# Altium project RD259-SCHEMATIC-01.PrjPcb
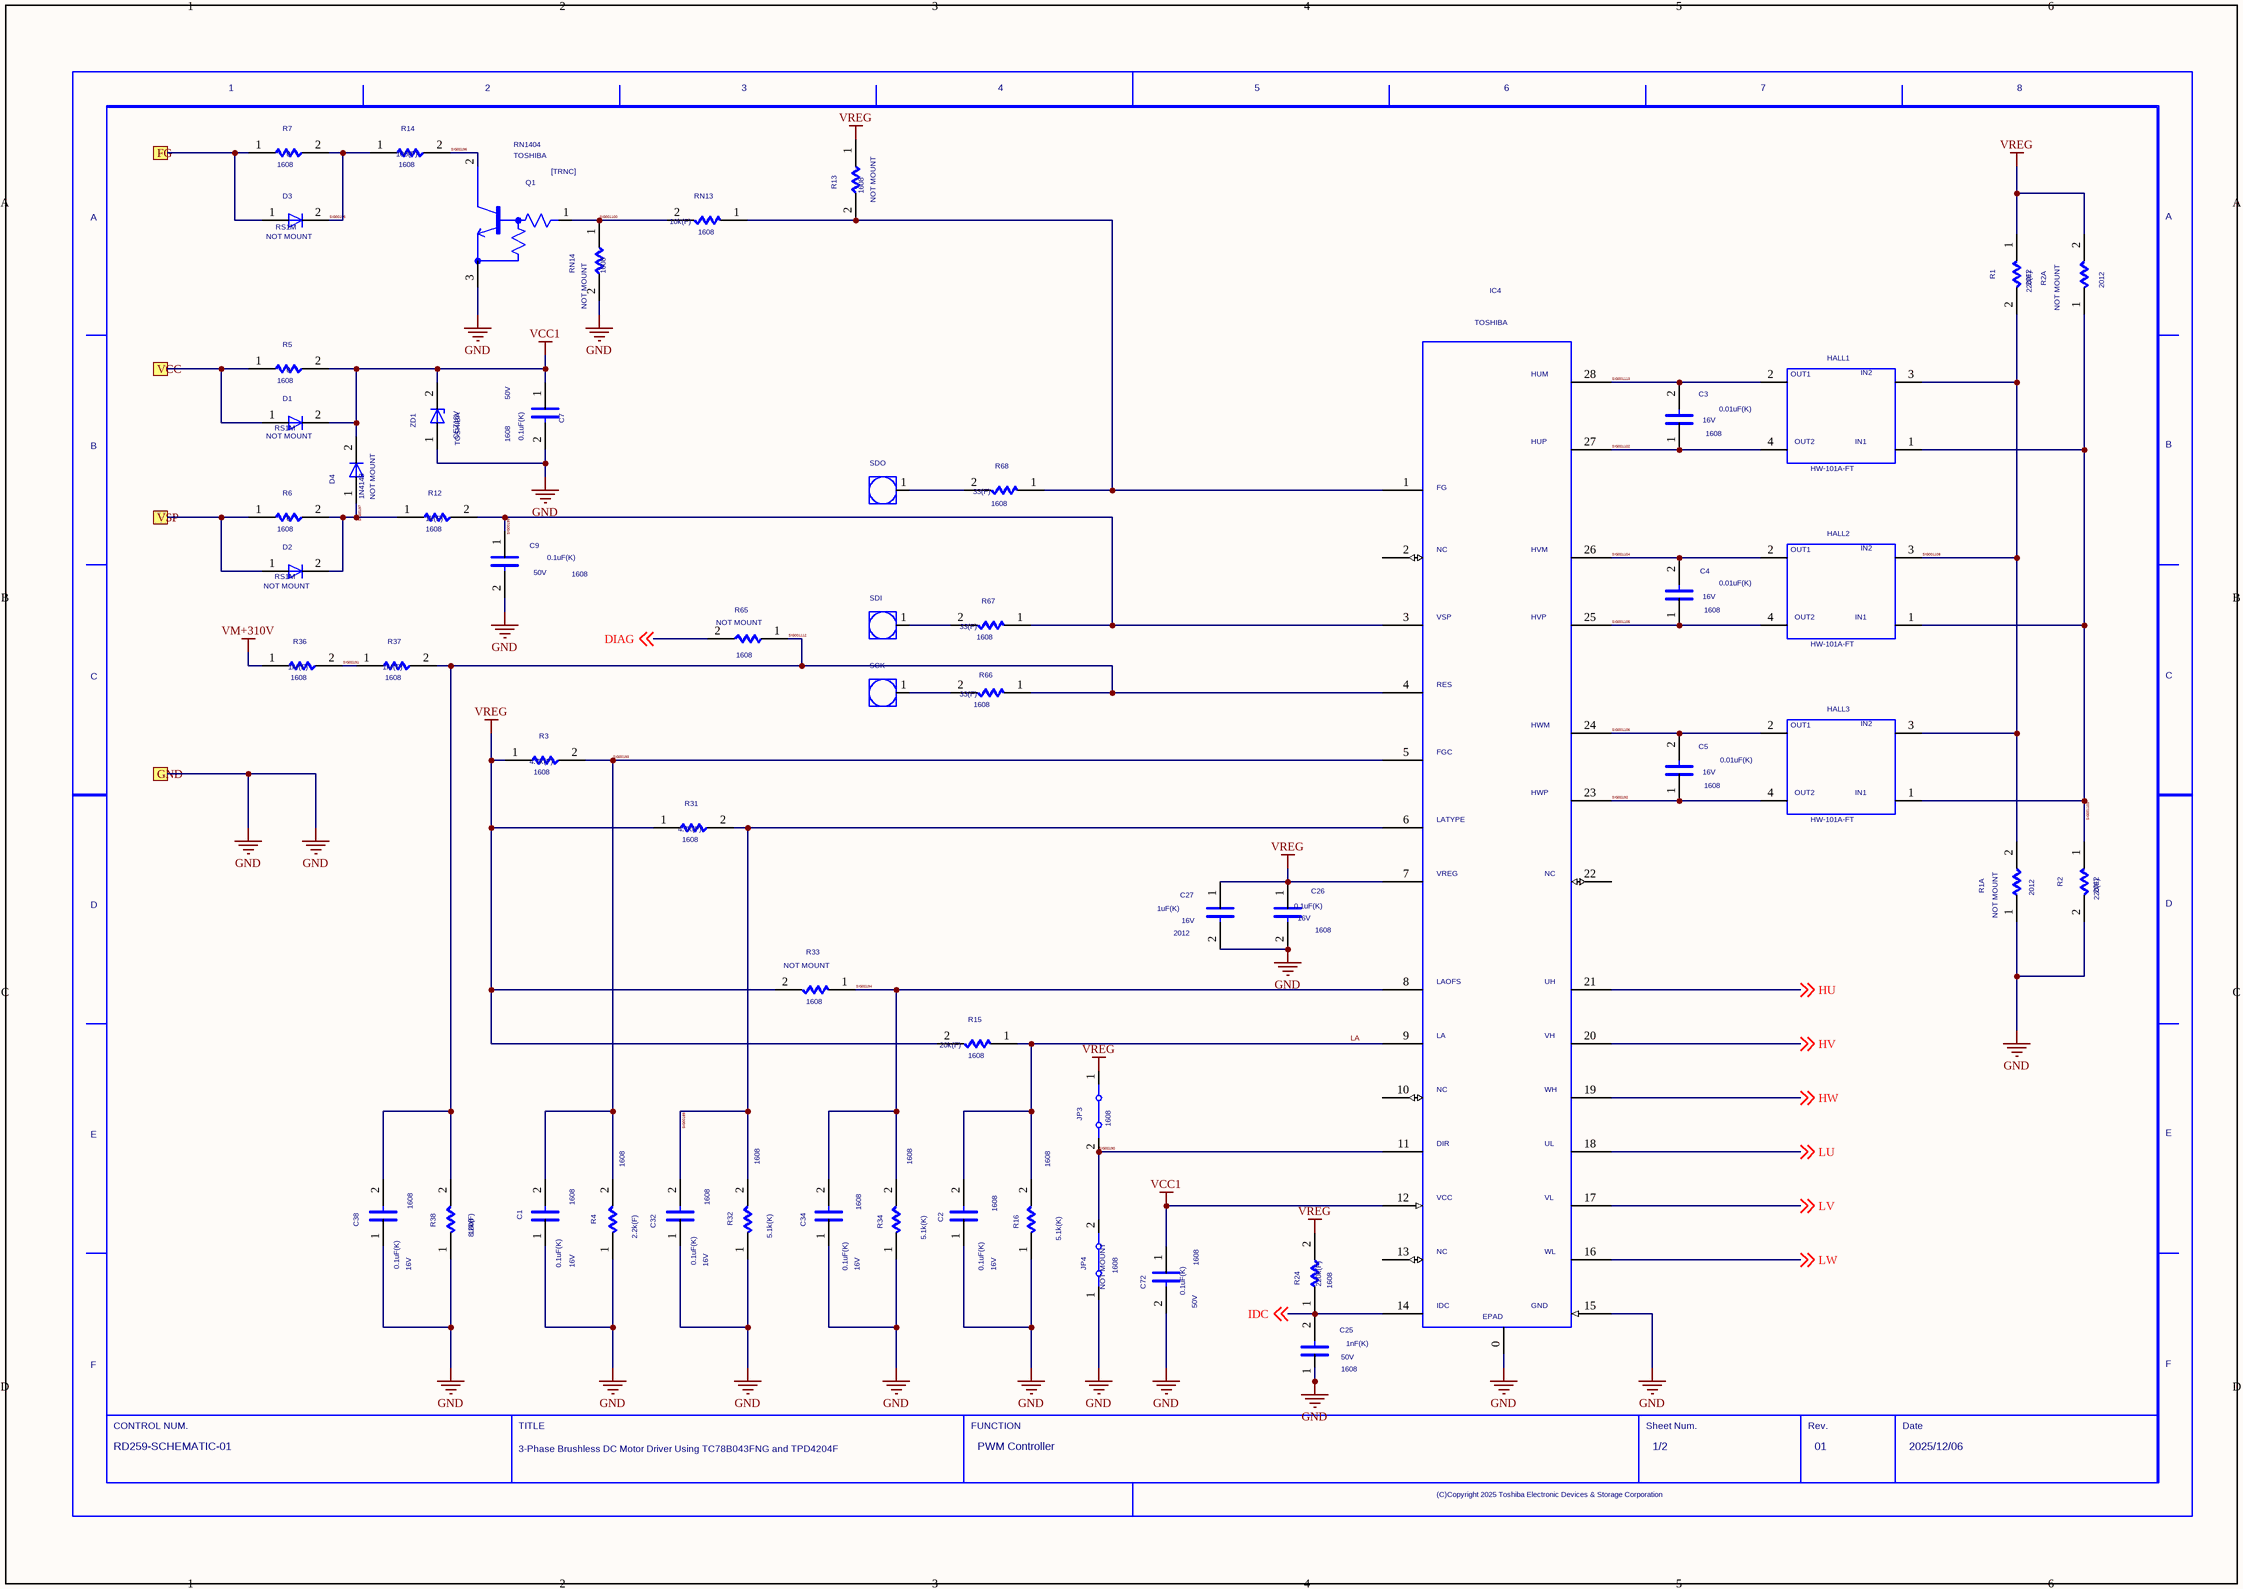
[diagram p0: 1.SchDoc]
2 sheets, 82 parts. Net scope: flat (ports and power ports of the same name join across sheets).
Sheets:
  1.SchDoc
  2.SchDoc

## Sheet 1.SchDoc
size 420 x 297 mm

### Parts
(Parts that share a designator on the sheet are numbered #1, #2 ... from top to bottom, then left to right.)
C1  VAL1: 0.1uF(K)  VAL2: 16V  SIZECODESMD: 1608  (hidden comment: C)
C2  VAL1: 0.1uF(K)  VAL2: 16V  SIZECODESMD: 1608  (hidden comment: C)
C3  VAL1: 0.01uF(K)  VAL2: 16V  SIZECODESMD: 1608  (hidden comment: C)
C4  VAL1: 0.01uF(K)  VAL2: 16V  SIZECODESMD: 1608  (hidden comment: C)
C5  VAL1: 0.01uF(K)  VAL2: 16V  SIZECODESMD: 1608  (hidden comment: C)
C7  VAL1: 0.1uF(K)  VAL2: 50V  SIZECODESMD: 1608  (hidden comment: C)
C9  VAL1: 0.1uF(K)  VAL2: 50V  SIZECODESMD: 1608  (hidden comment: C)
C25  VAL1: 1nF(K)  VAL2: 50V  SIZECODESMD: 1608  (hidden comment: C)
C26  VAL1: 0.1uF(K)  VAL2: 16V  SIZECODESMD: 1608  (hidden comment: C)
C27  VAL1: 1uF(K)  VAL2: 16V  SIZECODESMD: 2012  (hidden comment: C)
C32  VAL1: 0.1uF(K)  VAL2: 16V  SIZECODESMD: 1608  (hidden comment: C)
C34  VAL1: 0.1uF(K)  VAL2: 16V  SIZECODESMD: 1608  (hidden comment: C)
C38  VAL1: 0.1uF(K)  VAL2: 16V  SIZECODESMD: 1608  (hidden comment: C)
C72  VAL1: 0.1uF(K)  VAL2: 50V  SIZECODESMD: 1608  (hidden comment: C)
D1  VAL3: RS1M  NOTMNT: NOT MOUNT  (hidden comment: D)
D2  VAL3: RS1M  NOTMNT: NOT MOUNT  (hidden comment: D)
D3  NOTMNT: NOT MOUNT  VAL3: RS1M  (hidden comment: D)
D4  NOTMNT: NOT MOUNT  VAL3: 1N4148  (hidden comment: D)
HALL1  HW-101A-FT
HALL2  HW-101A-FT
HALL3  HW-101A-FT
IC4  USERCOMPTEXT3: TOSHIBA  (hidden comment: TC78B043FNG)
JP3  SIZECODESMD: 1608  (hidden comment: JP)
JP4  NOTMNT: NOT MOUNT  SIZECODESMD: 1608  (hidden comment: JP)
Q1  USERCOMPTEXT3: TOSHIBA  VAL3: RN1404  (hidden comment: TRNC)
R1  VAL1: 220(F)  SIZECODESMD: 2012  (hidden comment: R)
R1A  NOTMNT: NOT MOUNT  SIZECODESMD: 2012  (hidden comment: R)
R2  VAL1: 220(F)  SIZECODESMD: 2012  (hidden comment: R)
R2A  NOTMNT: NOT MOUNT  SIZECODESMD: 2012  (hidden comment: R)
R3  VAL1: 4.7k(F)  SIZECODESMD: 1608  (hidden comment: R)
R4  VAL1: 2.2k(F)  SIZECODESMD: 1608  (hidden comment: R)
R5  VAL1: 0  SIZECODESMD: 1608  (hidden comment: R)
R6  VAL1: 0  SIZECODESMD: 1608  (hidden comment: R)
R7  VAL1: 0  SIZECODESMD: 1608  (hidden comment: R)
R12  VAL1: 1k(F)  SIZECODESMD: 1608  (hidden comment: R)
R13  NOTMNT: NOT MOUNT  SIZECODESMD: 1608  (hidden comment: R)
R14  VAL1: 100(F)  SIZECODESMD: 1608  (hidden comment: R)
R15  VAL1: 20k(F)  SIZECODESMD: 1608  (hidden comment: R)
R16  VAL1: 5.1k(K)  SIZECODESMD: 1608  (hidden comment: R)
R24  VAL1: 220k(F)  SIZECODESMD: 1608  (hidden comment: R)
R31  VAL1: 4.7k(F)  SIZECODESMD: 1608  (hidden comment: R)
R32  VAL1: 5.1k(K)  SIZECODESMD: 1608  (hidden comment: R)
R33  NOTMNT: NOT MOUNT  SIZECODESMD: 1608  (hidden comment: R)
R34  VAL1: 5.1k(K)  SIZECODESMD: 1608  (hidden comment: R)
R36  VAL1: 1M(F)  SIZECODESMD: 1608  (hidden comment: R)
R37  VAL1: 1M(F)  SIZECODESMD: 1608  (hidden comment: R)
R38  VAL1: 8.2k(F)  SIZECODESMD: 1608  (hidden comment: R)
R65  NOTMNT: NOT MOUNT  SIZECODESMD: 1608  (hidden comment: R)
R66  VAL1: 33(F)  SIZECODESMD: 1608  (hidden comment: R)
R67  VAL1: 33(F)  SIZECODESMD: 1608  (hidden comment: R)
R68  VAL1: 33(F)  SIZECODESMD: 1608  (hidden comment: R)
RN13  VAL1: 10k(F)  SIZECODESMD: 1608  (hidden comment: R)
RN14  NOTMNT: NOT MOUNT  SIZECODESMD: 1608  (hidden comment: R)
SCK  PAD_FOR_BLDCS50  (value not drawn)
SDI  PAD_FOR_BLDCS50  (value not drawn)
SDO  PAD_FOR_BLDCS50  (value not drawn)
U?#1  DATE: 2025/12/06  DRAWINGNUMBER: RD259-SCHEMATIC-01  TITLE: 3-Phase Brushless DC Motor Driver / Using TC78B043FNG and TPD4204F  FUNCTION: PWM Controller  SHEETNUMBER: 1/2  REVISION: 01  (hidden comment: WAKU_DEF100)
ZD1  USERCOMPTEXT3: TOSHIBA  VAL3: CEZ18V  (hidden comment: ZD)

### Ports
FG, GND, VCC, VSP

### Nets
GND: C1.1 C2.1 C7.2 C9.2 C25.1 C26.2 C27.2 C32.1 C34.1 C38.1 C72.2 IC4.0 IC4.15 JP4.1 Q1.3(E) R1A.1 R2.2 R4.1 R16.1 R32.1 R34.1 R38.1 RN14.2 ZD1.1(A) ; port GND
VCC1: C7.1 C72.1 D1.2(C) D4.2(C) IC4.12 R5.2 ZD1.2(C)
VM+310V: R36.1
VREG: C26.1 C27.1 IC4.7 JP3.1 R1.1 R2A.2 R3.1 R13.1 R15.2 R24.2 R31.1 R33.2
DIAG: R65.2 ; off-sheet DIAG
FGOUT: IC4.1 R13.2 R68.1 RN13.1
HU: IC4.21 ; off-sheet HU
HV: IC4.20 ; off-sheet HV
HW: IC4.19 ; off-sheet HW
IDC: C25.2 IC4.14 R24.1 ; off-sheet IDC
LA: C2.2 IC4.9 R15.1 R16.2
LU: IC4.18 ; off-sheet LU
LV: IC4.17 ; off-sheet LV
LW: IC4.16 ; off-sheet LW
SCK: R66.2 SCK.1
SDI: R67.2 SDI.1
SIG00189: C32.2 IC4.6 R31.2 R32.2
SIG00190: IC4.11 JP3.2 JP4.2
SIG00191: R36.2 R37.1
SIG00192: C5.1 HALL3.4 IC4.23
SIG00193: C1.2 IC4.5 R3.2 R4.2
SIG00194: C34.2 IC4.8 R33.1 R34.2
SIG00195: D3.2(C) R7.2 R14.1
SIG00196: Q1.2(C) R14.2
SIG00197: D2.2(C) D4.1(A) R6.2 R12.1
SIG00198: R68.2 SDO.1
SIG00199: C9.1 IC4.3 R12.2 R67.1
SIG001100: Q1.1(B) RN13.2 RN14.1
SIG001102: C3.1 HALL1.4 IC4.27
SIG001103: HALL1.1 HALL2.1 HALL3.1 R2.1 R2A.1
SIG001104: C4.2 HALL2.2 IC4.26
SIG001105: C4.1 HALL2.4 IC4.25
SIG001106: C5.2 HALL3.2 IC4.24
SIG001108: HALL1.3 HALL2.3 HALL3.3 R1.2 R1A.2
SIG001112: C38.2 IC4.4 R37.2 R38.2 R65.1 R66.1
SIG001113: C3.2 HALL1.2 IC4.28
NetD1_1: D1.1(A) R5.1 ; port VCC
NetD2_1: D2.1(A) R6.1 ; port VSP
NetD3_1: D3.1(A) R7.1 ; port FG

Not connected (* = marked no-connect by the designer): IC4 2 10 13 22

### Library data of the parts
C1-C5 C7 C9 C25-C27 C32 C34 C38 C72 = C_Dup1: OriginalSymbolOrigin: (2540,7620); SAVECOUNT: 0
D1-D4 = D: SAVEAREA0: -225,-91,12804,7836; SAVECOUNT: 3; TIME: 14:49:55; UPDATEUSER: 19870035; UPDATETIME: 14:20:16; OriginalSymbolOrigin: (5080,5080)
HALL1-HALL3 = HW-101A-FT: SAVEAREA0: -12224,-318,37706,25614; TIME: 11:47:14; UPDATEUSER: t5459927; UPDATETIME: 12:34:57; SAVECOUNT: 11; OriginalSymbolOrigin: (5080,17780)
IC4 = TC78B043FNG: SAVEAREA0: -18325,-397,56528,38480; SAVECOUNT: 26; TIME: 12:23:18; UPDATEUSER: t5459927; UPDATETIME: 08:57:33; OriginalSymbolOrigin: (7620,190500)
JP3 JP4 = JP: OriginalSymbolOrigin: (2540,5080); SAVECOUNT: 0
Q1 = TRNC: OriginalSymbolOrigin: (2540,22860); SAVECOUNT: 0
R1-R4 R12 R14-R16 R24 R31 R32 R34 R36-R38 R66-R68 RN13 = R_Dup1: VAL2: 100mW; OriginalSymbolOrigin: (5080,5080); SAVECOUNT: 0
R1A R2A R33 = R_Dup1: OriginalSymbolOrigin: (5080,5080); SAVECOUNT: 0
R5-R7 = R_Dup1: OriginalSymbolOrigin: (5080,5080)
R13 R65 RN14 = R: OriginalSymbolOrigin: (5080,5080); SAVECOUNT: 0
SCK SDI SDO = PAD_FOR_BLDCS50: SAVEAREA0: -12224,-318,37706,25614; TIME: 11:47:14; UPDATEUSER: t5459927; UPDATETIME: 16:31:56; SAVECOUNT: 8; OriginalSymbolOrigin: (7620,17780); DEVICE: PAD
U?#1 = WAKU_DEF100: SAVEAREA0: -63393,-16950,474261,314592; TIME: 14:30:25; UPDATEUSER: t5459927; UPDATETIME: 15:25:21; SAVECOUNT: 3; OriginalSymbolOrigin: (10160,284480); SHTSAVECOUNT: 4
ZD1 = ZD: SAVEAREA0: -4630,-153,17114,13055; TIME: 14:49:55; UPDATEUSER: fukuda-y; UPDATETIME: 08:18:42; SAVECOUNT: 6; OriginalSymbolOrigin: (5080,5080)

## Sheet 2.SchDoc
size 420 x 297 mm
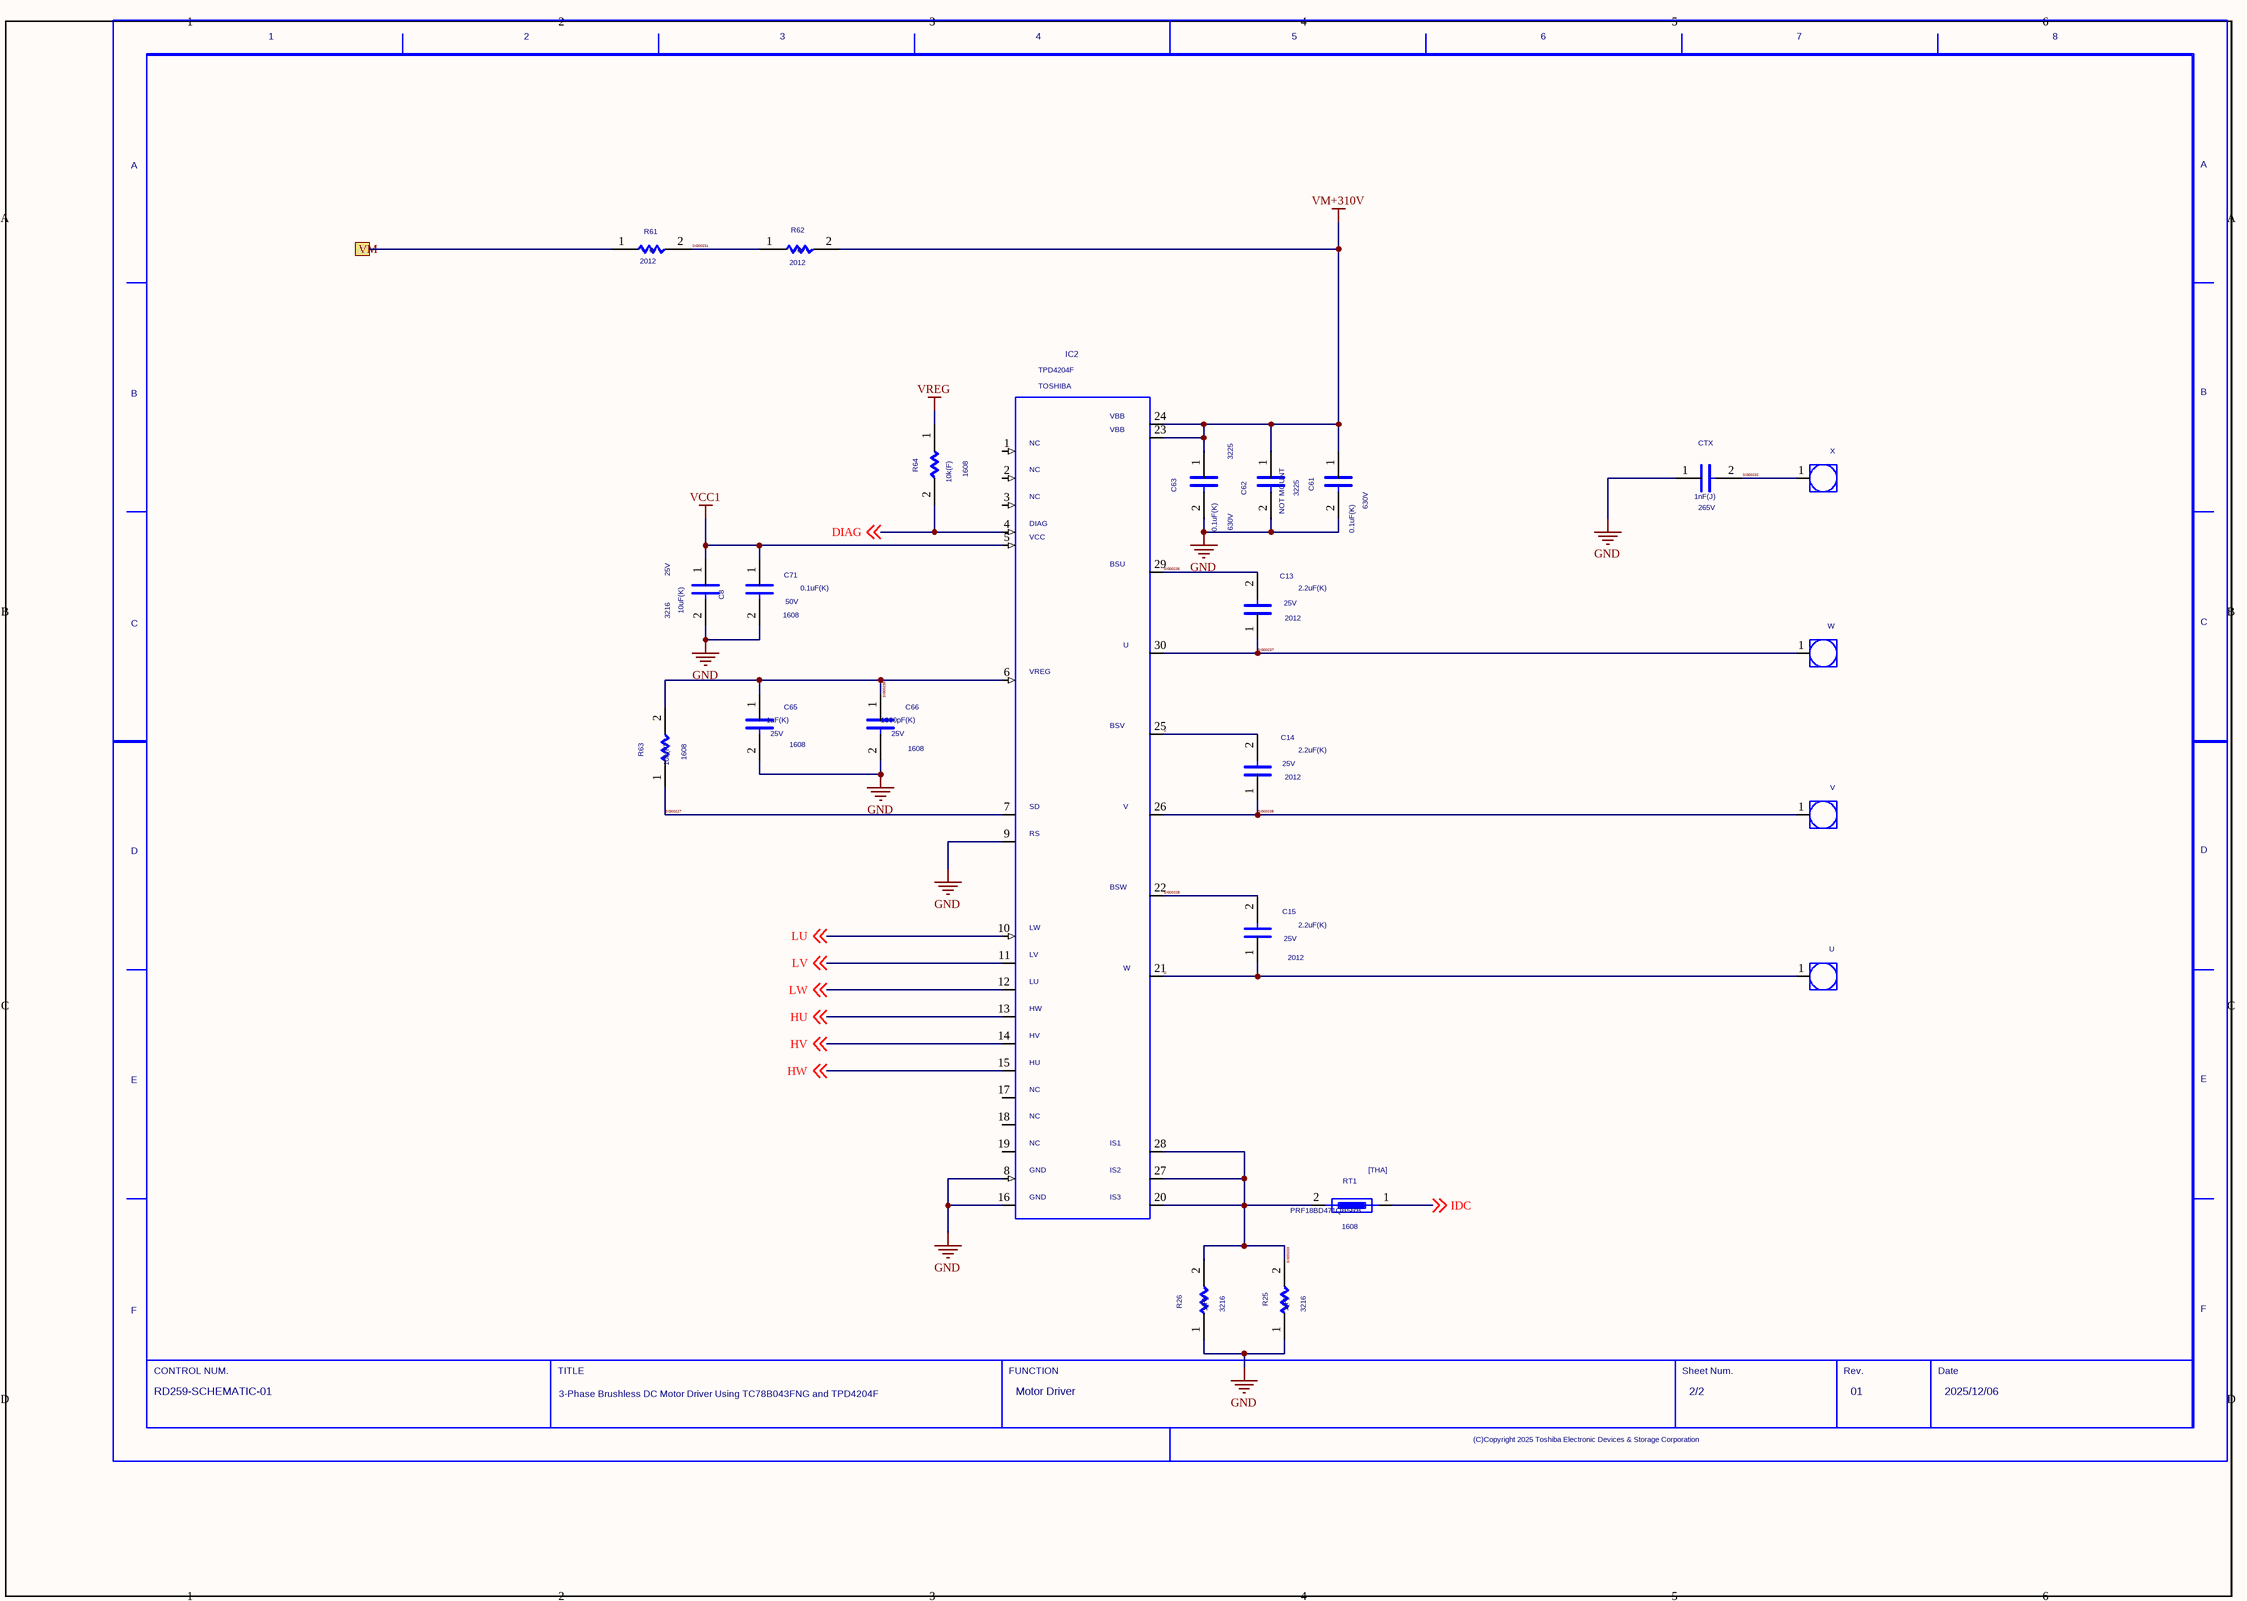
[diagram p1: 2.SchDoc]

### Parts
(Parts that share a designator on the sheet are numbered #1, #2 ... from top to bottom, then left to right.)
C8  VAL1: 10uF(K)  VAL2: 25V  SIZECODESMD: 3216  (hidden comment: C)
C13  VAL1: 2.2uF(K)  VAL2: 25V  SIZECODESMD: 2012  (hidden comment: C)
C14  VAL1: 2.2uF(K)  VAL2: 25V  SIZECODESMD: 2012  (hidden comment: C)
C15  VAL1: 2.2uF(K)  VAL2: 25V  SIZECODESMD: 2012  (hidden comment: C)
C61  VAL1: 0.1uF(K)  VAL2: 630V  (hidden comment: C)
C62  SIZECODESMD: 3225  NOTMNT: NOT MOUNT  (hidden comment: C)
C63  VAL1: 0.1uF(K)  VAL2: 630V  SIZECODESMD: 3225  (hidden comment: C)
C65  VAL1: 1uF(K)  VAL2: 25V  SIZECODESMD: 1608  (hidden comment: C)
C66  VAL1: 1000pF(K)  VAL2: 25V  SIZECODESMD: 1608  (hidden comment: C)
C71  VAL1: 0.1uF(K)  VAL2: 50V  SIZECODESMD: 1608  (hidden comment: C)
CTX  VAL1: 1nF(J)  VAL2: 265V  (hidden comment: C)
IC2  USERCOMPTEXT3: TOSHIBA  (hidden comment: TPD4204F)
R25  VAL1: 1(F)  SIZECODESMD: 3216  (hidden comment: R)
R26  VAL1: 1(F)  SIZECODESMD: 3216  (hidden comment: R)
R61  VAL1: 0  SIZECODESMD: 2012  (hidden comment: R)
R62  VAL1: 0  SIZECODESMD: 2012  (hidden comment: R)
R63  VAL1: 10k(F)  SIZECODESMD: 1608  (hidden comment: R)
R64  VAL1: 10k(F)  SIZECODESMD: 1608  (hidden comment: R)
RT1  SIZECODESMD: 1608  VAL3: PRF18BD471QB5RB  (hidden comment: THA)
U  PAD_FOR_BLDCS50  (value not drawn)
U?#2  DATE: 2025/12/06  DRAWINGNUMBER: RD259-SCHEMATIC-01  TITLE: 3-Phase Brushless DC Motor Driver / Using TC78B043FNG and TPD4204F  FUNCTION: Motor Driver  SHEETNUMBER: 2/2  REVISION: 01  (hidden comment: WAKU_DEF100)
V  PAD_FOR_BLDCS50  (value not drawn)
W  PAD_FOR_BLDCS50  (value not drawn)
X  PAD_FOR_BLDCS50  (value not drawn)

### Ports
VM

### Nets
GND: C8.2 C61.2 C62.2 C63.2 C65.2 C66.2 C71.2 CTX.1 IC2.8 IC2.9 IC2.16 R25.1 R26.1
VCC1: C8.1 C71.1 IC2.5
VM+310V: C61.1 C62.1 C63.1 IC2.23 IC2.24 R62.2
VREG: R64.1
DIAG: IC2.4 R64.2 ; off-sheet DIAG
HU: IC2.13 ; off-sheet HU
HV: IC2.14 ; off-sheet HV
HW: IC2.15 ; off-sheet HW
IDC: RT1.1 ; off-sheet IDC
LU: IC2.10 ; off-sheet LU
LV: IC2.11 ; off-sheet LV
LW: IC2.12 ; off-sheet LW
SIG00227: IC2.7 R63.1
SIG00228: C15.2 IC2.22
SIG00231: R61.2 R62.1
SIG00232: CTX.2 X.1
SIG00233: IC2.20 IC2.27 IC2.28 R25.2 R26.2 RT1.2
SIG00235: C65.1 C66.1 IC2.6 R63.2
SIG00236: C13.2 IC2.29
SIG00237: C13.1 IC2.30 W.1
SIG00238: C14.1 IC2.26 V.1
U: C15.1 IC2.21 U.1
V: C14.2 IC2.25
NetR61_1: R61.1 ; port VM

Not connected (* = marked no-connect by the designer): IC2 1 2 3 17 18 19

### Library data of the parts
C8 C61 C65 C66 C71 CTX = C_Dup1: as C1 on sheet 1
C13-C15 = C_Dup1: OriginalSymbolOrigin: (2540,7620); NOTMNT: MOUNT; USEWITHLAYOUT: YES; SAVECOUNT: 0
C62 = C: OriginalSymbolOrigin: (2540,7620); SAVECOUNT: 0
C63 = C_Dup1: OriginalSymbolOrigin: (2540,7620); USEWITHLAYOUT: YES; SAVECOUNT: 0
IC2 = TPD4204F: TIME: 16:32:01; UPDATEUSER: t5459927; UPDATETIME: 11:42:20; SAVECOUNT: 10; SAVEAREA0: -38352,-57023,57455,-16941; OriginalSymbolOrigin: (2540,154940)
R25 R26 = R_Dup1: VAL2: 500mW; OriginalSymbolOrigin: (5080,5080); SAVECOUNT: 0
R61 R62 = R_Dup1: OriginalSymbolOrigin: (5080,5080)
R63 = R_Dup1: as R1 on sheet 1
R64 = R: VAL2: 100mW; OriginalSymbolOrigin: (5080,5080); SAVECOUNT: 0
RT1 = THA: SAVECOUNT: 3; SAVEAREA0: -562,-143,15615,10489; TIME: 16:37:29; UPDATEUSER: sato-yr; OriginalSymbolOrigin: (2540,5080)
U V W X = PAD_FOR_BLDCS50: as SCK on sheet 1
U?#2 = WAKU_DEF100: SAVEAREA0: -63393,-16950,474261,314592; TIME: 14:30:25; UPDATEUSER: t5459927; UPDATETIME: 15:25:20; SAVECOUNT: 3; OriginalSymbolOrigin: (10160,284480)

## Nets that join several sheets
GND: 1 (24 pins), 2 (13 pins)
VCC1: 1 (7 pins), 2 (C8.1 C71.1 IC2.5)
VM+310V: 1 (R36.1), 2 (6 pins)
VREG: 1 (12 pins), 2 (R64.1)
DIAG: 1 (R65.2), 2 (IC2.4 R64.2)
HU: 1 (IC4.21), 2 (IC2.13)
HV: 1 (IC4.20), 2 (IC2.14)
HW: 1 (IC4.19), 2 (IC2.15)
IDC: 1 (C25.2 IC4.14 R24.1), 2 (RT1.1)
LU: 1 (IC4.18), 2 (IC2.10)
LV: 1 (IC4.17), 2 (IC2.11)
LW: 1 (IC4.16), 2 (IC2.12)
